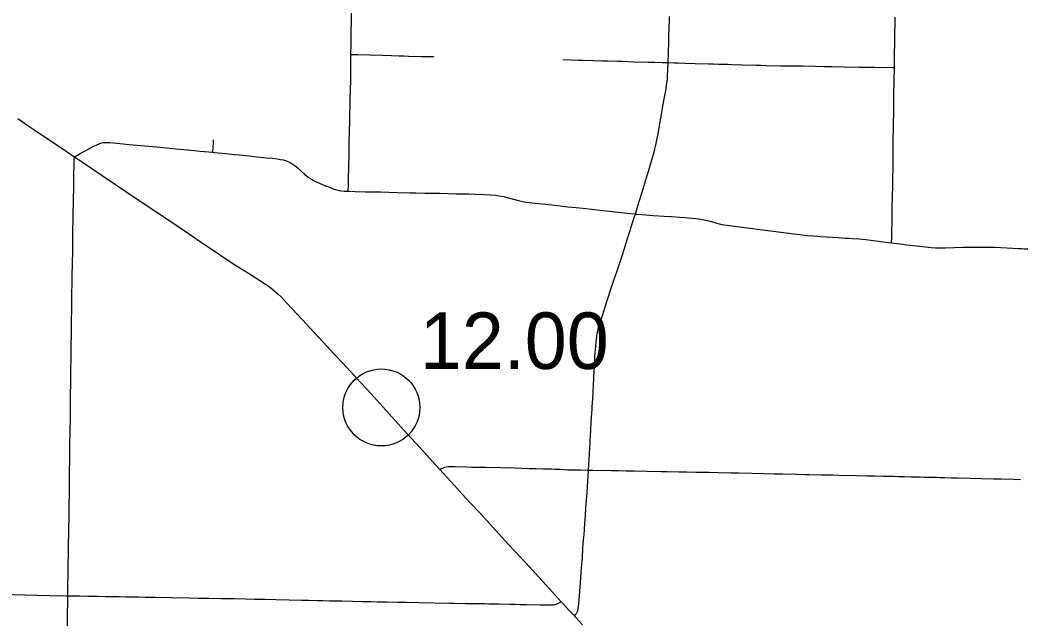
# Model space of a CAD drawing. Extents: x 1813937 to 1948437, y 826606 to 1022856.
# Drawn here: x 1890191 to 1909677, y 915824 to 927491 of the extents above; entities that cross this region are included whole.
import ezdxf

# ---------------------------------------------------------------- set-up
doc = ezdxf.new("R2010")
doc.units = 0
for name, color, linetype in [('Default', 7, 'Continuous'), ('GM_X_County_Road', 7, 'Continuous'), ('GM_X_State_Route', 7, 'Continuous'), ('GM_X_Township_Road', 7, 'Continuous')]:
    doc.layers.add(name, color=color, linetype=linetype)

msp = doc.modelspace()

# ---------------------------------------------------------------- linework, layer by layer
at = {"layer": 'Default'}
msp.add_circle((1897233, 919944), 750, dxfattribs=at)
at = {"layer": 'GM_X_County_Road'}
for points in [[(1902822, 926661), (1902833, 927050), (1902836, 927165), (1902841, 927362), (1902845, 927476), (1902850, 927558)], [(1902183, 923712), (1902237, 923889), (1902335, 924202), (1902382, 924359), (1902426, 924500), (1902473, 924657), (1902538, 924878), (1902564, 924973), (1902582, 925053), (1902602, 925149), (1902625, 925278), (1902700, 925698), (1902725, 925844), (1902750, 925989), (1902773, 926118), (1902797, 926264), (1902806, 926329), (1902811, 926394), (1902818, 926525), (1902822, 926661)], [(1891252, 924826), (1891313, 924861), (1891362, 924889), (1891471, 924948), (1891543, 924987), (1891600, 925018), (1891643, 925041), (1891687, 925062), (1891733, 925080), (1891779, 925096), (1891811, 925103), (1891843, 925106), (1891875, 925107), (1891940, 925104), (1892022, 925096), (1892316, 925067), (1892626, 925039), (1892855, 925018), (1893230, 924982), (1893459, 924961), (1893704, 924938), (1893952, 924915)], [(1893952, 924915), (1893952, 924934), (1893955, 924995), (1893963, 925122), (1893964, 925156)], [(1893952, 924915), (1893982, 924912), (1894194, 924891), (1894373, 924873), (1894455, 924865), (1894667, 924843), (1894749, 924835), (1894879, 924821), (1894993, 924809), (1895107, 924797), (1895204, 924786), (1895269, 924775), (1895317, 924764), (1895364, 924751), (1895409, 924734), (1895454, 924714), (1895496, 924690), (1895537, 924663), (1895576, 924634), (1895612, 924603), (1895624, 924592), (1895659, 924559), (1895672, 924548), (1895731, 924493), (1895769, 924461), (1895808, 924431), (1895849, 924403), (1895891, 924378), (1895950, 924347), (1896025, 924313), (1896146, 924262), (1896253, 924219), (1896315, 924198), (1896362, 924184), (1896410, 924173), (1896459, 924165), (1896508, 924160), (1896574, 924156), (1896587, 924155)], [(1896587, 924155), (1896721, 924150), (1896918, 924147), (1897213, 924141), (1897541, 924133), (1897787, 924126), (1897902, 924124), (1898082, 924120), (1898164, 924119), (1898377, 924115), (1898689, 924108), (1898935, 924102), (1899066, 924098), (1899230, 924091), (1899360, 924083), (1899458, 924076), (1899523, 924069), (1899571, 924061), (1899619, 924051), (1899683, 924034), (1899809, 924000), (1899905, 923976), (1899985, 923957), (1900049, 923944), (1900114, 923934), (1900163, 923928), (1900359, 923908), (1900554, 923888), (1900766, 923865), (1900864, 923855), (1901027, 923839), (1901158, 923824), (1901386, 923801), (1901614, 923775), (1901908, 923743), (1901973, 923735), (1902087, 923722), (1902177, 923713), (1902183, 923712)], [(1901270, 918725), (1901278, 918832), (1901283, 918931), (1901295, 919160), (1901300, 919248), (1901303, 919310), (1901306, 919374), (1901309, 919427), (1901312, 919485), (1901316, 919547), (1901320, 919633), (1901337, 919844), (1901340, 919877), (1901341, 919909), (1901343, 919958), (1901353, 920119), (1901366, 920379), (1901381, 920657), (1901385, 920738), (1901390, 920853), (1901395, 920935), (1901410, 921147), (1901418, 921228), (1901429, 921326), (1901440, 921390), (1901450, 921438), (1901466, 921502), (1901490, 921580), (1901541, 921736), (1901581, 921861), (1901615, 921970), (1901640, 922048), (1901707, 922250), (1901765, 922421), (1901827, 922608), (1901880, 922763), (1901930, 922919), (1902029, 923232), (1902079, 923388), (1902109, 923482), (1902174, 923685), (1902182, 923709), (1902183, 923712)], [(1902183, 923712), (1902211, 923710), (1902316, 923701), (1902528, 923686), (1902741, 923671), (1902889, 923662), (1903052, 923650), (1903150, 923644), (1903281, 923634), (1903362, 923627), (1903411, 923621), (1903459, 923613), (1903523, 923600), (1903587, 923584), (1903666, 923564), (1903745, 923542), (1903840, 923517), (1903904, 923503), (1903969, 923492), (1904213, 923460), (1904473, 923429), (1904555, 923418), (1904669, 923403), (1904815, 923383), (1905124, 923343), (1905270, 923324), (1905384, 923311), (1905531, 923295), (1905645, 923284), (1905793, 923273), (1906022, 923259), (1906136, 923252), (1906267, 923244), (1906349, 923240), (1906415, 923236), (1906545, 923227), (1906676, 923214), (1906773, 923202), (1906871, 923190), (1907115, 923158), (1907174, 923151)], [(1907174, 923151), (1907342, 923130), (1907473, 923114), (1907783, 923079), (1907946, 923061), (1908028, 923054), (1908093, 923053), (1908225, 923054), (1908569, 923063), (1908766, 923067), (1908881, 923068), (1909061, 923068), (1909176, 923067), (1909307, 923062), (1909421, 923055), (1909651, 923040), (1909715, 923038), (1909764, 923035), (1909828, 923032), (1909839, 923031)], [(1901179, 917433), (1901182, 917459), (1901190, 917573), (1901198, 917688), (1901208, 917835), (1901218, 917982), (1901228, 918129), (1901240, 918293), (1901262, 918604), (1901270, 918725)], [(1900994, 915884), (1901020, 915916), (1901030, 915929), (1901040, 915943), (1901047, 915958), (1901054, 915973), (1901059, 915989), (1901068, 916021), (1901077, 916069), (1901083, 916118), (1901090, 916200), (1901100, 916364), (1901112, 916527), (1901122, 916641), (1901134, 916821), (1901149, 917017), (1901161, 917214), (1901173, 917361), (1901179, 917433)]]:
    msp.add_lwpolyline(points, dxfattribs=at)
at = {"layer": 'GM_X_State_Route'}
for points in [[(1890146, 925571), (1890346, 925437)], [(1890346, 925437), (1890459, 925361), (1890704, 925196), (1891044, 924967), (1891153, 924893), (1891252, 924826), (1891412, 924720), (1891792, 924463), (1892051, 924289), (1892255, 924152), (1892514, 923978), (1892895, 923721), (1893031, 923630), (1893331, 923428), (1893494, 923318), (1893806, 923107), (1893915, 923034), (1894079, 922925), (1894243, 922815), (1894393, 922716), (1894643, 922559), (1894713, 922516), (1894866, 922420), (1894976, 922348), (1895029, 922310), (1895121, 922240), (1895171, 922198), (1895220, 922154), (1895278, 922096), (1895381, 921989), (1895504, 921858), (1895783, 921557), (1895917, 921413), (1896184, 921124), (1896211, 921095)], [(1896211, 921095), (1896329, 920967), (1896475, 920811), (1896709, 920559), (1896821, 920439), (1896955, 920295), (1897275, 919942), (1897384, 919821), (1897738, 919433), (1897981, 919166), (1898366, 918744), (1898445, 918657), (1898655, 918426), (1898810, 918257), (1898965, 918088), (1899155, 917883), (1899397, 917616), (1899708, 917278), (1899831, 917145), (1900110, 916845), (1900366, 916568), (1900443, 916483), (1900620, 916289), (1900739, 916161), (1900776, 916121), (1900888, 915999)], [(1900888, 915999), (1900994, 915884), (1901009, 915867), (1901154, 915711)]]:
    msp.add_lwpolyline(points, dxfattribs=at)
at = {"layer": 'GM_X_Township_Road'}
for points in [[(1896649, 927459), (1896650, 927519), (1896653, 927715), (1896659, 927928), (1896662, 928091), (1896665, 928239), (1896668, 928337), (1896672, 928484), (1896677, 928696), (1896681, 928860), (1896682, 928879)], [(1907231, 926563), (1907233, 926758), (1907239, 927119), (1907240, 927233), (1907242, 927413), (1907242, 927544)], [(1896641, 926822), (1896642, 927012), (1896644, 927127), (1896646, 927225), (1896647, 927306), (1896649, 927401)], [(1896649, 927401), (1896649, 927459)], [(1896587, 924155), (1896589, 924187), (1896591, 924251), (1896592, 924300), (1896594, 924382), (1896600, 924644), (1896604, 924857), (1896608, 925087), (1896615, 925349), (1896618, 925497), (1896620, 925644), (1896624, 925824), (1896626, 925889), (1896632, 926168), (1896635, 926283), (1896637, 926365), (1896639, 926495), (1896640, 926561), (1896641, 926822)], [(1896641, 926822), (1896774, 926819), (1897005, 926812), (1897252, 926805), (1897433, 926801), (1897581, 926795), (1897680, 926791), (1897762, 926789), (1898009, 926781), (1898091, 926779), (1898239, 926777), (1898256, 926776)], [(1900772, 926721), (1900936, 926713), (1901067, 926711), (1901165, 926708), (1901362, 926701), (1901526, 926696), (1901641, 926694), (1901838, 926689), (1901937, 926686), (1902150, 926679), (1902429, 926671), (1902558, 926668), (1902703, 926665), (1902822, 926661)], [(1902822, 926661), (1902833, 926660), (1902937, 926658), (1903019, 926656), (1903151, 926652), (1903347, 926645), (1903610, 926638), (1903708, 926635), (1903807, 926632), (1903987, 926628), (1904069, 926626), (1904266, 926620), (1904528, 926612), (1904627, 926608), (1904725, 926605), (1905019, 926598), (1905117, 926597), (1905183, 926595), (1905248, 926595), (1905363, 926595), (1905445, 926595), (1905691, 926591), (1905871, 926587), (1906019, 926586), (1906249, 926580), (1906544, 926575), (1906840, 926570), (1907201, 926563), (1907231, 926563)], [(1907174, 923151), (1907176, 923186), (1907178, 923219), (1907180, 923317), (1907182, 923415), (1907185, 923530), (1907186, 923693), (1907188, 923841), (1907193, 924054), (1907199, 924267), (1907201, 924398), (1907204, 924628), (1907205, 924742), (1907207, 924988), (1907209, 925185), (1907210, 925332), (1907211, 925398), (1907214, 925545), (1907216, 925627), (1907218, 925726), (1907221, 925922), (1907221, 926004), (1907228, 926348), (1907231, 926529), (1907231, 926563)], [(1891124, 916277), (1891124, 916290), (1891124, 916306), (1891124, 916328), (1891124, 916354), (1891124, 916387), (1891125, 916420), (1891125, 916448), (1891125, 916481), (1891125, 916513), (1891126, 916544), (1891126, 916581), (1891127, 916615), (1891128, 916656), (1891129, 916684), (1891129, 916722), (1891130, 916781), (1891131, 916831), (1891132, 916875), (1891133, 916906), (1891133, 916931), (1891133, 916963), (1891134, 917013), (1891136, 917095), (1891134, 917258), (1891135, 917308), (1891136, 917324), (1891139, 917372), (1891140, 917405), (1891142, 917421), (1891142, 917453), (1891142, 917469), (1891142, 917485), (1891141, 917500), (1891142, 917517), (1891143, 917549), (1891145, 917631), (1891148, 917762), (1891150, 917959), (1891155, 918369), (1891158, 918648), (1891162, 918976), (1891165, 919254), (1891168, 919451), (1891173, 919762), (1891173, 919811), (1891173, 919910), (1891174, 920057), (1891177, 920188), (1891178, 920257), (1891180, 920352), (1891181, 920432), (1891182, 920538), (1891184, 920659), (1891185, 920745), (1891186, 920845), (1891188, 920950), (1891189, 921052), (1891190, 921135), (1891191, 921217), (1891192, 921300), (1891193, 921383), (1891195, 921473), (1891195, 921539), (1891196, 921594), (1891196, 921610), (1891196, 921642), (1891197, 921708), (1891199, 921773), (1891201, 921936), (1891201, 921969), (1891202, 922018), (1891203, 922051), (1891204, 922100), (1891204, 922132), (1891203, 922147), (1891203, 922162), (1891203, 922179), (1891204, 922228), (1891205, 922293), (1891207, 922391), (1891208, 922457), (1891210, 922555), (1891214, 922702), (1891217, 922817), (1891219, 922915), (1891222, 923046), (1891223, 923128), (1891223, 923210), (1891223, 923308), (1891224, 923455), (1891225, 923537), (1891226, 923651), (1891227, 923716), (1891228, 923765), (1891232, 923880), (1891233, 923945), (1891232, 923994), (1891233, 924010), (1891234, 924043), (1891238, 924174), (1891239, 924237), (1891240, 924319), (1891242, 924412), (1891243, 924519), (1891244, 924605), (1891246, 924705), (1891248, 924779), (1891252, 924826)], [(1898366, 918744), (1898441, 918770), (1898472, 918781), (1898504, 918788), (1898537, 918792), (1898586, 918794), (1898668, 918793), (1898898, 918785), (1898996, 918783), (1899259, 918778), (1899554, 918772), (1899833, 918765), (1899964, 918761), (1900112, 918758), (1900243, 918754), (1900390, 918750), (1900554, 918747), (1900620, 918745), (1900718, 918740), (1900800, 918735), (1900865, 918732), (1900996, 918728), (1901111, 918727), (1901242, 918725), (1901270, 918725)], [(1901270, 918725), (1901357, 918723), (1901718, 918717), (1901849, 918714), (1901997, 918713), (1902161, 918710), (1902407, 918705), (1902686, 918697), (1902800, 918696), (1903030, 918691), (1903178, 918689), (1903358, 918685), (1903490, 918684), (1903621, 918681), (1903801, 918676), (1904047, 918673), (1904195, 918670), (1904457, 918665), (1904687, 918658), (1904884, 918653), (1905048, 918650), (1905327, 918642), (1905491, 918638), (1905573, 918637), (1905802, 918634), (1905884, 918633), (1906032, 918629), (1906147, 918626), (1906491, 918617), (1906704, 918614), (1906852, 918611), (1907016, 918608), (1907213, 918603), (1907311, 918601), (1907360, 918600), (1907426, 918598), (1907556, 918595), (1907638, 918592), (1907720, 918590), (1907802, 918587), (1907884, 918586), (1907999, 918584), (1908048, 918584), (1908113, 918582), (1908212, 918579), (1908343, 918575), (1908457, 918572), (1908704, 918564), (1908933, 918560), (1909163, 918556), (1909310, 918552), (1909557, 918546), (1909688, 918543)], [(1888346, 916330), (1888809, 916322), (1889334, 916313), (1889728, 916306), (1890056, 916299), (1890761, 916284), (1891090, 916278), (1891124, 916277)], [(1891083, 913706), (1891086, 913892), (1891088, 914056), (1891093, 914384), (1891094, 914436), (1891095, 914497), (1891096, 914543), (1891097, 914601), (1891098, 914682), (1891099, 914738), (1891100, 914809), (1891101, 914872), (1891102, 914923), (1891103, 914982), (1891104, 915047), (1891105, 915121), (1891106, 915168), (1891107, 915220), (1891111, 915366), (1891119, 915841), (1891119, 915923), (1891121, 916152), (1891124, 916277)], [(1891124, 916277), (1891172, 916276), (1891352, 916274), (1891516, 916270), (1891713, 916267), (1891861, 916265), (1892123, 916260), (1892254, 916257), (1892353, 916256), (1892500, 916253), (1892632, 916251), (1892829, 916250), (1893140, 916245), (1893485, 916237), (1893666, 916232), (1893879, 916230), (1894109, 916225), (1894371, 916221), (1894584, 916216), (1894765, 916211), (1894962, 916207), (1895175, 916203), (1895438, 916197), (1895684, 916192), (1895815, 916189), (1895979, 916185), (1896094, 916182), (1896225, 916179), (1896356, 916176), (1896471, 916175), (1896668, 916171), (1896865, 916167), (1897029, 916163), (1897160, 916160), (1897341, 916158), (1897341, 916158)], [(1897341, 916158), (1897554, 916154), (1897702, 916150), (1897964, 916146), (1898555, 916135), (1898653, 916132), (1898867, 916125), (1898981, 916123), (1899064, 916124), (1899129, 916125), (1899244, 916124), (1899326, 916122), (1899424, 916119), (1899523, 916117), (1899735, 916112), (1899834, 916111), (1899932, 916109), (1900063, 916106), (1900326, 916103), (1900523, 916100), (1900573, 916102), (1900588, 916103), (1900606, 916106), (1900621, 916109), (1900638, 916113), (1900654, 916118), (1900668, 916123), (1900685, 916131), (1900711, 916145), (1900739, 916161)]]:
    msp.add_lwpolyline(points, dxfattribs=at)

# ---------------------------------------------------------------- texts
at = {"layer": 'Default'}
msp.add_text('12.00', height=1100, dxfattribs=at).set_placement((1897983, 920694))

doc.saveas('drawing.dxf')
